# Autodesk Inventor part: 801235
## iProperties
Created: 2007-10
Part Number: 801235
Document SubType Name: Modeling
Designer: TH
Density: 7.86 g/cm^3
Mass: 12.3393 g
Surface Area: 14.5331 cm^2
Volume: 1.56989 cm^3
Material: Steel, Mild
Description: NUT R2456 - M12
Component Category: Fasteners
Author: TH
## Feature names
1. Extrusion1
2. Revolution1
3. Revolution2
